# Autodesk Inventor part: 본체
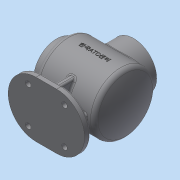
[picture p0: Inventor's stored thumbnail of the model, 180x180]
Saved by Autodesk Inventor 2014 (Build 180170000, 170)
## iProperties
Created: 2023-01
Part Number: 본체
Material: 일반
Document SubType Name: Modeling
Designer: dg
Density: 1 g/cm^3
Appearance: 기본값
Author: dg
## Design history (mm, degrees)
sketch "스케치1"
  geometry: L1 (-61, 0)-(61, 0); L2 (-61, 38)-(-49, 38); L3 (-49, 38)-(-49, 50); L4 (-49, 50)-(50.087, 50); L5 (-61, 38)-(-61, 27); L6 (-44, 27)-(-44, 45); L7 (-44, 45)-(46.83, 45); L8 (-61, 27)-(-44, 27); A1 r 120 centre (-59, 0) between (61, 0) and (50.087, 50); A2 r 115 centre (-59, 0) between (56, 0) and (46.83, 45); 2 further points
  constraints: 16 end point, 4 point on circle, 3 parallel, 2 centre point, 2 coincident, 2 perpendicular, 2 point on line, 1 horizontal, 1 midpoint, 1 vertical alignment, 2 other
  dimensions: "d0" = 122 distance of L1.start L1.end; "d1" = 100 diameter of L4 L1; "d2" = 76 diameter of L2 L1; "d4" = 120 radius of A1; "d5" = 110 distance from line of L1.end L3; "d6" = 5 radial gap between concentric circles of A1 A2; "d58" = 54 diameter of L8 L1
revolve "회전1" sketch "스케치1" stored, may be unused: angle "d7" = 90 deg
node "작업 평면1"
sketch "스케치2"
  geometry: L1 (61, 38)-(61, -38) reference; C1 r 38 at (-2, 0); C2 r 27 at (-2, 0); 1 further point
  constraints: 2 centre point, 2 coincident
  dimensions: "d9" = 76 diameter of C1; "d10" = 54 diameter of C2; "d72" = 63 distance from line of L1 point (-2, 0)
extrude "돌출1" join sketch "스케치2" stored distance "d11" = 10; taper "d12" = 0 deg
extrude "돌출2" cut sketch "스케치2" stored distance "d13" = 10; taper "d14" = 0 deg
node "작업 평면2"
sketch "스케치3"
  geometry: L1 (-61, -46)-(65, -46); L2 (65, -46)-(65, 46); L3 (65, 46)-(-61, 46); L4 (-61, 46)-(-61, -46); L5 (-61, -46)-(65, 46); L6 (65, -46)-(-61, 46); L7 (-61, -38)-(-61, 38) reference; 3 further points
  constraints: 12 end point, 3 midpoint, 2 parallel, 1 horizontal, 1 horizontal alignment, 1 perpendicular, 1 point on line
  dimensions: "d16" = 126 distance of L2.end L3.end; "d17" = 92 distance of L1.end L2.end
extrude "돌출3" join sketch "스케치3" distance "d18" = 10; taper "d19" = 0 deg
fillet "모깎기1" dims "d20" = 46
fillet "모깎기2" dims "d21" = 3
chamfer "모따기1" distance "d22" = 1; stored, may be unused: second distance "d23" = 2, angle "d24" = 45 deg
fillet "모깎기3" dims "d44" = 8
sketch "스케치7"
  geometry: C1 r 28 at (0, 0) reference; 1 further point
  constraints: 1 vertical alignment
  dimensions: "d47" = 32.5 distance of C1.centre point (0, 32.5)
hole "구멍1" sketch "스케치7" at (0, 32.5) diameter "d48" = 3.242; stored, may be unused: countersink angle "d52" = 90 deg, drill point angle "d54" = 118 deg; dims "d49" = 8, "d50" = 4, "d51" = 2, "d53" = 10
sketch "스케치8"
  geometry: C1 r 38 at (0, 0) reference; 1 further point
  constraints: 1 vertical alignment
  dimensions: "d59" = 32.5 distance of C1.centre point (0, 32.5)
hole "구멍2" sketch "스케치8" at (0, 32.5) diameter "d60" = 3.242; stored, may be unused: countersink angle "d64" = 90 deg, drill point angle "d66" = 118 deg; dims "d61" = 8, "d62" = 4, "d63" = 2, "d65" = 10
node "작업 평면3"
sketch "스케치9"
  geometry: L1 (27, 63)-(28, 64) reference; L2 (28, 64)-(30.879, 64) reference; L3 (30.879, 64)-(30.879, 54) reference; L4 (30.879, 54)-(32.5, 53.026) reference; L5 (32.5, 53.026)-(34.121, 54) reference; L6 (34.121, 54)-(34.121, 64) reference; L7 (34.121, 64)-(38, 64) reference; L8 (38, 64)-(38, 33.586) reference; L9 (-38, 33.586)-(-38, 64) reference; L10 (-38, 64)-(-34.121, 64) reference; L11 (-34.121, 64)-(-34.121, 54) reference; L12 (-34.121, 54)-(-32.5, 53.026) reference; L13 (-32.5, 53.026)-(-30.879, 54) reference; L14 (-30.879, 54)-(-30.879, 64) reference; L15 (-30.879, 64)-(-28, 64) reference; L16 (-28, 64)-(-27, 63) reference; L17 (-27, 63)-(-27, 36) reference; L18 (27, 36)-(27, 63) reference; L19 (46, -73)-(46, -80) reference; L20 (46, -80)-(-46, -80) reference; L21 (-46, -80)-(-46, -73) reference; L22 (-43, -70)-(43, -70) reference; L23 (-35, -35.707)-(-35, -70); L24 (-35, -70)-(35, -70); L25 (35, -70)-(35, -35.707); A1 r 50 centre (0, 0) between (-38.679, 31.685) and (38.679, 31.685) reference; A2 r 45 centre (0, 0) between (-27, 36) and (27, 36) reference; A3 r 3 centre (43, -73) between (46, -73) and (43, -70) reference; A4 r 3 centre (-43, -73) between (-43, -70) and (-46, -73) reference; 2 further points
  constraints: 6 end point, 2 perpendicular, 2 point on circle, 2 point on line, 1 midpoint, 1 parallel, 1 vertical alignment, 2 other
  dimensions: "d74" = 35 distance from line of point (0, 0) L23
extrude "돌출6" join sketch "스케치9" stored distance "d75" = 10; taper "d76" = 0 deg
sketch "스케치10"
  geometry: L1 (-41, -45)-(44.827, -45) reference; L2 (44.827, 45)-(29, 45) reference; L3 (29, 45)-(29, 63) reference; L4 (29, 63)-(30, 64) reference; L5 (30, 64)-(32.879, 64) reference; L6 (32.879, 64)-(32.879, 54) reference; L7 (32.879, 54)-(34.5, 53.026) reference; L8 (34.5, 53.026)-(36.121, 54) reference; L9 (36.121, 54)-(36.121, 64) reference; L10 (36.121, 64)-(40, 64) reference; L11 (40, 64)-(40, 53) reference; L12 (43, 50)-(44.827, 50) reference; L13 (44.827, -50)-(7, -50) reference; L14 (7, -50)-(7, -70) reference; L15 (7, -70)-(62, -70) reference; L16 (65, -73)-(65, -80) reference; L17 (65, -80)-(-61, -80) reference; L18 (-61, -80)-(-61, -73) reference; L19 (-58, -70)-(-3, -70) reference; L20 (-3, -70)-(-3, -50) reference; L21 (-3, -50)-(-41, -50) reference; L22 (-49, -42)-(-49, -41) reference; L23 (-52, -38)-(-61, -38) reference; L24 (-61, -38)-(-61, -34.121) reference; L25 (-61, -34.121)-(-51, -34.121) reference; L26 (-51, -34.121)-(-50.026, -32.5) reference; L27 (-50.026, -32.5)-(-51, -30.879) reference; L28 (-51, -30.879)-(-61, -30.879) reference; L29 (-61, -30.879)-(-61, -28) reference; L30 (-61, -28)-(-60, -27) reference; L31 (-60, -27)-(-44, -27) reference; L32 (-44, -27)-(-44, -42) reference; L33 (-44, 42)-(-44, 27) reference; L34 (-44, 27)-(-60, 27) reference; L35 (-60, 27)-(-61, 28) reference; L36 (-61, 28)-(-61, 30.879) reference; L37 (-61, 30.879)-(-51, 30.879) reference; L38 (-51, 30.879)-(-50.026, 32.5) reference; L39 (-50.026, 32.5)-(-51, 34.121) reference; L40 (-51, 34.121)-(-61, 34.121) reference; L41 (-61, 34.121)-(-61, 38) reference; L42 (-61, 38)-(-52, 38) reference; L43 (-49, 41)-(-49, 42) reference; L44 (-41, 50)-(-39, 50) reference; L45 (-36, 53)-(-36, 64) reference; L46 (-36, 64)-(-32.121, 64) reference; L47 (-32.121, 64)-(-32.121, 54) reference; L48 (-32.121, 54)-(-30.5, 53.026) reference; L49 (-30.5, 53.026)-(-28.879, 54) reference; L50 (-28.879, 54)-(-28.879, 64) reference; L51 (-28.879, 64)-(-26, 64) reference; L52 (-26, 64)-(-25, 63) reference; L53 (-25, 63)-(-25, 45) reference; L54 (-25, 45)-(-41, 45) reference; L55 (-38, -70)-(-32.641, -50); A1 r 3 centre (-41, -42) between (-44, -42) and (-41, -45) reference; A2 r 3 centre (44.827, -42) between (44.827, -45) and (47.608, -43.125) reference; A3 r 115 centre (-59, 0) between (47.608, -43.125) and (47.608, 43.125) reference; A4 r 3 centre (44.827, 42) between (47.608, 43.125) and (44.827, 45) reference; A5 r 8 centre (44.827, 42) between (52.243, 45) and (44.827, 50) reference; A6 r 120 centre (-59, 0) between (52.243, -45) and (52.243, 45) reference; A7 r 8 centre (44.827, -42) between (44.827, -50) and (52.243, -45) reference; A8 r 3 centre (62, -73) between (65, -73) and (62, -70) reference; A9 r 3 centre (-58, -73) between (-58, -70) and (-61, -73) reference; A10 r 8 centre (-41, -42) between (-49, -42) and (-41, -50) reference; A11 r 3 centre (-52, -41) between (-49, -41) and (-52, -38) reference; A12 r 3 centre (-41, 42) between (-41, 45) and (-44, 42) reference; A13 r 3 centre (-52, 41) between (-52, 38) and (-49, 41) reference; A14 r 8 centre (-41, 42) between (-41, 50) and (-49, 42) reference; 1 further point
  constraints: 2 end point, 2 point on line, 2 other
  dimensions: "d77" = 105 deg angle of L19 L55; "d78" = 23 distance from line of L18 L55.start
feature "리브2" sketch "스케치10" dims "d79" = 1, "d80" = 10, "d81" = 0, "d82" = 0, "d83" = 1, "d84" = 1
fillet "모깎기6" dims "d85" = 3
fillet "모깎기7" dims "d86" = 3
node "작업 평면4"
sketch "스케치11"
  geometry: L1 (-61.544, -38)-(-61.544, 38) reference; L2 (64.456, -80)-(18.456, -80) reference; 2 further points
  constraints: 1 other
  dimensions: "d87" = 63 distance from line of L1 point (1.456, 0); "d88" = 80 distance from line of L2 point (1.456, 0)
feature "엠보싱1" sketch "스케치11" dims "d0" = 122, "d1" = 100, "d2" = 76, "d4" = 120, "d5" = 110, "d6" = 5, "d58" = 54, "d89" = 0.5, "d90" = 0
sketch "스케치12"
  geometry: L1 (0, -38)-(4, -38) reference; L2 (-40.302, 2)-(-40.302, -2) reference; C1 r 4.5 at (-28, -30); 2 further points
  constraints: 2 midpoint, 1 centre point
  dimensions: "d91" = 9 diameter of C1; "d92" = 30 horizontal distance of point (2, -38) C1.centre; "d93" = 30 vertical distance of C1.centre point (-40.302, 0)
extrude "돌출7" cut sketch "스케치12" distance "d94" = 10; taper "d95" = 0 deg
node "솔리드1"
pattern_circular "원형 패턴1" dims angle "d56" = 360 deg
pattern_circular "원형 패턴2" dims angle "d68" = 360 deg
mirror "대칭3"
mirror "대칭4"
mirror "대칭5"
node "절단 모서리 투영4"
node "절단 모서리 투영5"
other parameters: "d8" = 64, "d73" = -63
